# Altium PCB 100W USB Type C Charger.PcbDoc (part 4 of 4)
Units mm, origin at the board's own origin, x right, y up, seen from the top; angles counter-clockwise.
Board outline 79.45 x 55.68 mm, 4 copper layers (Top Layer, Signal Layer 1, Signal Layer 2, Bottom Layer), stack 1.565 mm thick; 161 components, 84 nets, 462 pads, 2175 vias.
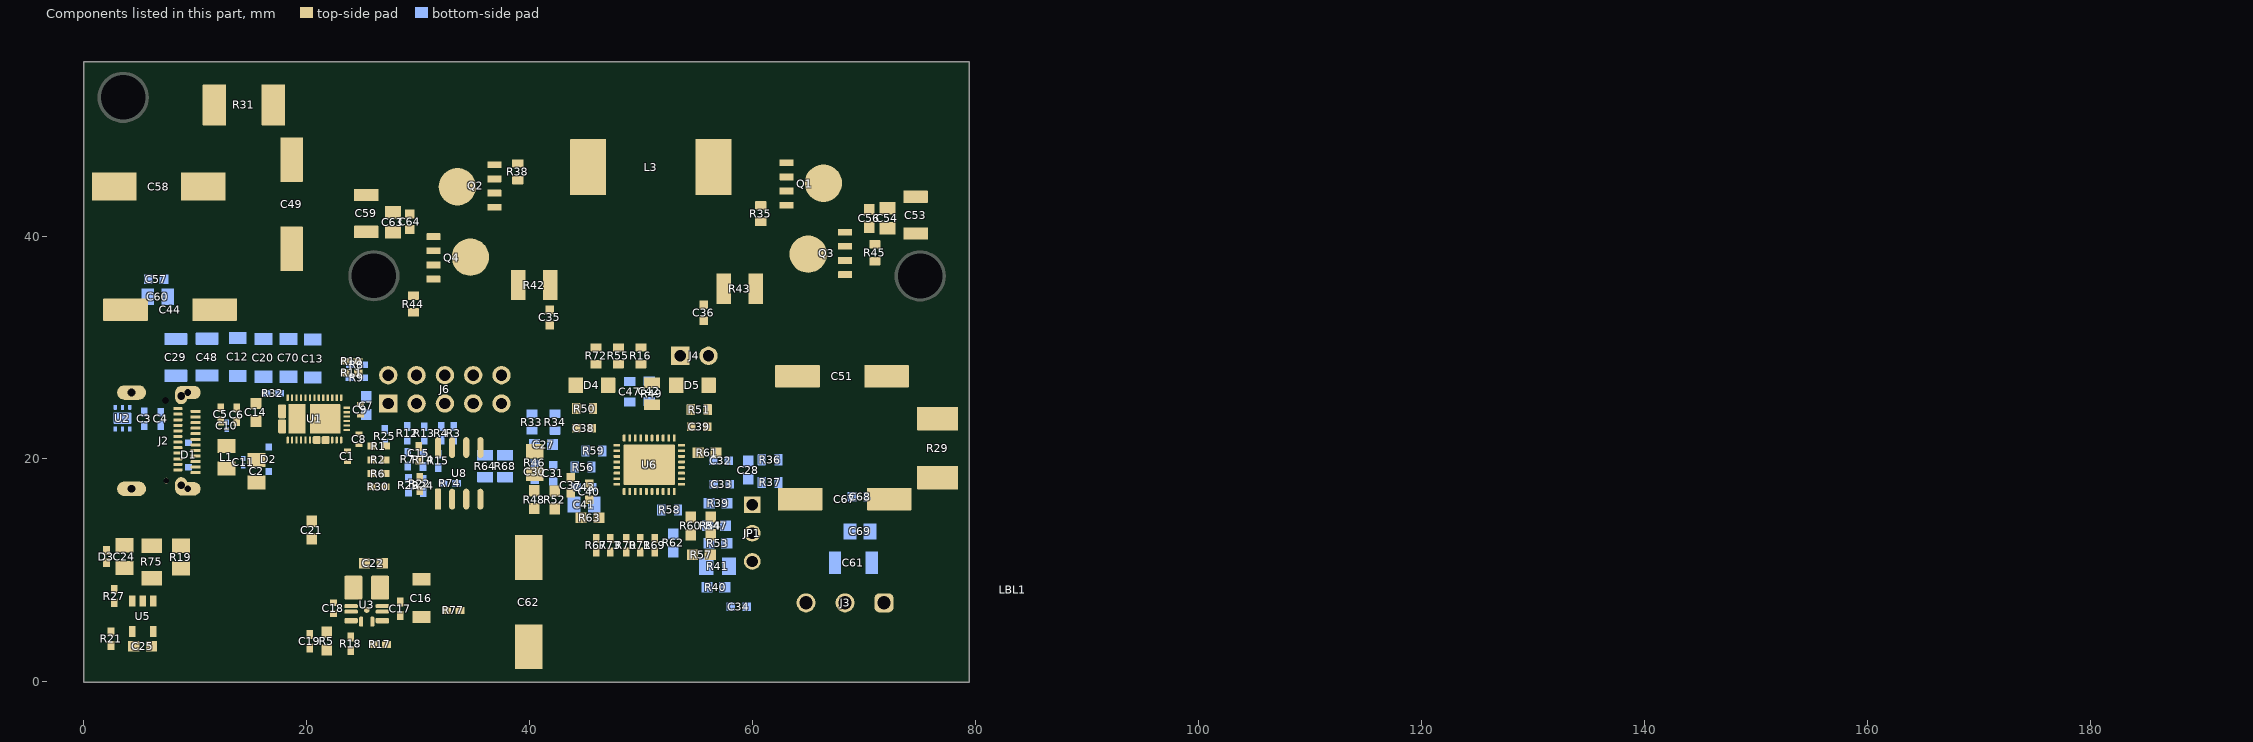
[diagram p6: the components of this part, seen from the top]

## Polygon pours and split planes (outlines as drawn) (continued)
P_OUT on Top Layer "TOP_LAYER_P_OUT_P025" (solid, remove dead copper, pour order 25): 64.308,55.009 64.308,42.909 65.504,41.712 78.892,41.712 78.892,55.009
BAT on Top Layer "TOP_LAYER_BAT_P031" (solid, remove dead copper, pour order 31): 69.769,19.315 69.769,3.891 78.786,3.891 78.786,19.315
PGND on Top Layer "TOP_LAYER_PGND_P051" (solid, remove dead copper, pour order 51): 20.124,28.919 20.088,22.281 22.294,22.281 22.294,18.928 24.265,16.29 29.666,16.29 30.674,14.94 35.587,14.94 38.268,17.523 38.323,28.919
PGND on Top Layer "TOP_LAYER_PGND_P070" (solid, remove dead copper, pour order 70): 40.305,29.689 40.305,15.334 45.197,10.441 59.614,10.441 59.614,29.689
PPHV on Top Layer "TOP_LAYER_PPHV_P010" (solid, remove dead copper, pour order 10): 8.093,29.311 14.717,29.311 14.717,22.461 19.339,22.461 19.339,27.565 21.505,29.722 21.505,34.447 8.093,34.447
PPHV on Top Layer "TOP_LAYER_PPHV_P011" (solid, remove dead copper, pour order 11): 8.237,55.009 8.237,41.433 13.317,41.433 13.317,55.009
VSYS on Top Layer "TOP_LAYER_VSYS_P013" (solid, remove dead copper, pour order 13): 35.556,55.009 35.556,41.255 15.374,41.255 15.374,55.009
SW1 on Top Layer "TOP_LAYER_SW1_P018" (solid, remove dead copper, pour order 18): 32.415,40.281 32.415,33.152 49.512,33.152 49.512,55.25 36.016,55.25 36.016,40.843 35.455,40.281
PGND on Top Layer "TOP_LAYER_PGND_P026" (solid, remove dead copper, pour order 26): 67.192,34.129 64.032,30.969 64.032,29.571 78.892,29.571 78.892,41.255 67.723,41.255 67.084,40.616
PGND on Top Layer "TOP_LAYER_PGND_P007" (solid, remove dead copper, pour order 7): 0.686,55.021 0.686,24.017 10.641,24.017 10.92,24.017 14.476,24.017 14.776,24.283 16.099,24.283 16.099,25.696 14.476,25.696 14.476,26.406 14.476,29.009 7.878,29.009 7.878,55.021
P_OUT on Top Layer "TOP_LAYER_P_OUT_P030" (solid, remove dead copper, pour order 30): 69.799,28.47 70.346,29.018 78.786,29.018 78.786,22.312 69.783,22.312
PGND on Top Layer "TOP_LAYER_PGND_P032" (solid, remove dead copper, pour order 32): 7.605,40.896 7.605,34.611 32.169,34.611 32.169,40.896
PGND on Top Layer "TOP_LAYER_PGND_P035" (solid, remove dead copper, pour order 35): 21.748,38.067 21.748,29.376 66.296,29.139 66.296,32.646 32.071,32.646 32.071,38.067
VBUS on Top Layer "TOP_LAYER_VBUS_P043" (solid, remove dead copper, pour order 43): 14.493,22.357 14.493,20.557 13.708,19.773 11.783,19.773 11.783,18.414 12.004,18.192 13.708,18.182 14.342,18.799 17.532,18.799 17.553,17.682 19.47,17.67 21.233,19.434 21.233,22.067 20.489,22.067 20.489,21.331 18.136,21.331 18.136,23.517 17.397,23.517 17.397,22.796 16.958,22.357
PGND on Top Layer "TOP_LAYER_PGND_P048" (solid, remove dead copper, pour order 48): 60.467,5.213 69.022,5.213 69.022,28.658 70.5,30.023 70.5,31.02 60.467,31.02
PGND on Bottom Layer "BOTTOM_LAYER_PGND_P088" (solid, remove dead copper, pour order 88): 39.728,29.238 39.728,15.063 44.575,10.216 60.138,10.216 60.138,29.238
PGND on Bottom Layer "BOTTOM_LAYER_PGND_P017" (solid, remove dead copper, pour order 17): 67.403,41.239 67.403,34.326 66.478,33.401 66.192,33.115 60.644,33.02 60.492,22.193 69.866,22.193 69.753,41.239
PGND on Bottom Layer "BOTTOM_LAYER_PGND_P004" (solid, remove dead copper, pour order 4): 0.341,55.709 0.537,20.782 2.256,20.782 2.256,23.157 3.091,23.157 4.268,23.157 5.063,23.766 11.382,23.776 11.382,22.968 14.513,22.968 14.513,24.375 16.032,24.375 16.494,24.837 23.951,24.837 23.951,29.715 7.033,29.715 6.312,30.436 6.312,55.709
PPHV on Bottom Layer "BOTTOM_LAYER_PPHV_P015" (solid, pour order 15): 6.843,30.622 7.743,29.722 21.67,29.722 21.67,31.606 18.829,34.447 15.548,34.447 13.317,36.678 13.317,55.009 6.843,55.009
P_OUT on Bottom Layer "BOTTOM_LAYER_P_OUT_P020" (solid, remove dead copper, pour order 20): 70.016,42.672 70.016,22.312 78.892,22.312 78.892,42.672
PGND on Bottom Layer "BOTTOM_LAYER_PGND_P047" (solid, remove dead copper, pour order 47): 36.901,30.126 38.942,28.086 38.942,16.008 37.632,14.698 24.322,14.698 23.874,15.146 23.874,30.126
Vdrain on Bottom Layer "BOTTOM_LAYER_VDRAIN_P045" (solid, remove dead copper, pour order 45): 18.233,25.023 18.233,22.432 19.784,22.432 19.786,22.434 19.786,25.032 19.759,25.059 18.269,25.059
PGND on Bottom Layer "BOTTOM_LAYER_PGND_P001" (solid, remove dead copper, pour order 1): 19.919,25.529 19.919,15.222 24.11,15.222 24.11,25.529
PPHV on Bottom Layer "BOTTOM_LAYER_PPHV_P003" (solid, remove dead copper, pour order 3): 14.726,22.871 17.403,22.871 18.194,23.708 18.183,25.024 16.857,25.024 16.016,24.183 14.726,24.183
P_OUT on Bottom Layer "BOTTOM_LAYER_P_OUT_P016" (solid, remove dead copper, pour order 16): 64.308,54.793 64.308,42.909 65.504,41.712 78.892,41.712 78.892,54.793
BAT on Bottom Layer "BOTTOM_LAYER_BAT_P021" (solid, remove dead copper, pour order 21): 70.016,20.265 70.016,5.695 78.768,5.695 78.768,20.265
PGND on Bottom Layer "BOTTOM_LAYER_PGND_P022" (solid, remove dead copper, pour order 22): 60.787,20.287 60.787,5.826 69.643,5.826 69.643,20.287
VSYS on Bottom Layer "BOTTOM_LAYER_VSYS_P023" (solid, remove dead copper, pour order 23): 35.587,55.009 35.587,41.122 14.868,41.122 14.868,55.009
SW1 on Bottom Layer "BOTTOM_LAYER_SW1_P024" (solid, remove dead copper, pour order 24): 32.669,40.543 32.669,33.152 49.512,33.152 49.512,55.009 36.016,55.009 36.016,41.058 35.501,40.543
SW2 on Bottom Layer "BOTTOM_LAYER_SW2_P027" (solid, remove dead copper, pour order 27): 60.874,33.203 65.28,33.203 67.102,35.025 67.102,40.259 66.121,41.239 65.403,41.239 63.774,42.868 63.774,55.009 52.217,55.009 52.217,33.203
PGND on Bottom Layer "BOTTOM_LAYER_PGND_P028" (solid, remove dead copper, pour order 28): 42.554,28.148 58.649,28.148 58.649,32.646 42.554,32.646
PGND on Bottom Layer "BOTTOM_LAYER_PGND_P034" (solid, remove dead copper, pour order 34): 14.868,37.677 17.063,35.405 19.742,35.29 23.506,31.526 32.038,31.526 32.038,40.8 14.868,40.8
PGND on Bottom Layer "BOTTOM_LAYER_PGND_P036" (solid, remove dead copper, pour order 36): 0.686,15.598 24.123,15.598 24.123,15.01 38.529,15.01 43.72,9.819 78.729,9.574 78.729,0.488 0.7,0.488
PGND on Bottom Layer "BOTTOM_LAYER_PGND_P038" (solid, remove dead copper, pour order 38): 2.28,19.548 2.28,20.968 0.686,20.968 0.686,15.508 20.274,15.508 20.274,19.611
NetC3_1 on Bottom Layer "BOTTOM_LAYER_NETC3_1_P000" (solid, remove dead copper, pour order 0): 2.493,22.908 2.493,19.756 11.148,19.756 11.148,23.581 5.168,23.581 4.495,22.908
BAT on Bottom Solder "NONET_L-01_P-001" (solid): 70.394,18.007 70.394,8.64 78.547,8.64 78.547,18.007
no net on Bottom Solder "NONET_L-01_P-001" (solid): 70.454,44.898 70.454,40.086 78.729,40.086 78.729,44.898
no net on Bottom Solder "NONET_L-01_P-001" (solid): 11.679,0.627 18.888,0.627 18.888,4.228 11.679,4.228
no net on Bottom Solder "NONET_L-01_P-001" (solid): 39.938,0.627 77.655,0.627 77.655,4.453 39.938,4.453
no net on Bottom Solder "NONET_L-01_P-001" (solid): 26.727,0.627 54.212,0.627 54.212,9.191 26.727,9.191
PGND on Bottom Solder "NONET_L-01_P-001" (solid): 17.88,13.948 24.557,13.948 24.557,18.673 17.88,18.673
PGND on Bottom Solder "NONET_L-01_P-001" (solid): 24.019,3.648 37.616,3.648 37.616,14.174 24.019,14.174
PGND on Bottom Solder "NONET_L-01_P-001" (solid): 10.852,9.837 20.268,9.837 20.268,17.579 10.852,17.579
no net on Bottom Solder "NONET_L-01_P-001" (solid): 70.459,31.445 70.459,23.372 78.612,23.372 78.612,31.445
SW1 on Bottom Solder "NONET_L-01_P-001" (solid): 32.977,39.863 32.977,33.735 39.525,33.735 39.525,39.863
no net on Bottom Solder "NONET_L-01_P-001" (solid): 36.643,54.564 36.643,46.643 44.2,46.643 44.2,54.564
PGND on Bottom Solder "NONET_L-01_P-001" (solid): 18.299,0.627 24.665,0.627 24.665,14.174 18.299,14.174
SW1 on Bottom Solder "NONET_L-01_P-001" (solid): 41.83,54.564 41.83,33.76 49.078,33.76 49.078,54.564
no net on Bottom Solder "NONET_L-01_P-001" (solid): 52.743,45.796 52.743,34.114 59.393,34.114 59.393,45.796
SW2 on Bottom Solder "NONET_L-01_P-001" (solid): 52.742,54.564 52.742,44.341 63.042,44.341 63.042,54.564
P_OUT on Bottom Solder "NONET_L-01_P-001" (solid): 64.841,54.564 64.841,43.007 65.795,42.054 78.768,42.054 78.768,54.564
VSYS on Bottom Solder "NONET_L-01_P-001" (solid): 15.451,54.564 15.451,42.194 34.806,42.194 34.806,54.564
no net on Top Solder "TOP_LAYER_PGND_P050" (solid): 20.407,15.65 22.425,15.65 22.425,17.955 20.407,17.955
no net on Top Solder "TOP_LAYER_PGND_P050" (solid): 70.395,3.704 78.105,3.704 78.105,14.381 70.395,14.381
VSYS on Top Solder "TOP_LAYER_PGND_P050" (solid): 15.679,49.459 20.193,49.459 20.193,54.651 15.679,54.651
VSYS on Top Solder "TOP_LAYER_PGND_P050" (solid): 19.987,44.43 30.196,44.43 30.196,47.909 19.987,47.909
BAT on Top Solder "TOP_LAYER_PGND_P050" (solid): 42.344,1.001 78.034,1.001 78.034,4.303 42.344,4.303
PGND on Top Solder "TOP_LAYER_PGND_P050" (solid): 72.763,34.145 78.593,34.145 78.593,39.549 72.763,39.549
PGND on Top Solder "TOP_LAYER_PGND_P050" (solid): 68.341,29.952 78.603,29.952 78.603,35.355 68.341,35.355
PGND on Top Solder "TOP_LAYER_PGND_P050" (solid): 22.282,29.722 28.301,29.722 28.301,39.519 22.282,39.519
PGND on Top Solder "TOP_LAYER_PGND_P050" (solid): 43.725,30.842 68.588,30.842 68.588,32.423 43.725,32.423
PGND on Top Solder "TOP_LAYER_PGND_P050" (solid): 26.566,29.712 43.905,29.712 43.905,32.388 26.566,32.388
SW2 on Top Solder "TOP_LAYER_PGND_P050" (solid): 56.677,48.326 63.459,48.326 63.459,54.64 56.677,54.64
SW1 on Top Solder "TOP_LAYER_PGND_P050" (solid): 36.634,48.24 42.901,48.24 42.901,54.564 36.634,54.564
SW1 on Top Solder "TOP_LAYER_PGND_P050" (solid): 42.057,38.112 48.743,38.112 48.743,54.564 42.057,54.564
SW2 on Top Solder "TOP_LAYER_PGND_P050" (solid): 52.776,38.067 59.207,38.067 59.207,54.64 52.776,54.64
VSYS on Top Solder "TOP_LAYER_PGND_P050" (solid): 20.001,46.854 34.874,46.854 34.874,54.64 20.001,54.64
P_OUT on Top Solder "TOP_LAYER_PGND_P050" (solid): 64.834,47.472 71.782,47.472 71.782,54.564 64.834,54.564
P_OUT on Top Solder "TOP_LAYER_PGND_P050" (solid): 69.781,43.619 78.278,43.619 78.278,54.564 69.781,54.564
PGND on Signal Layer 1 "SIGNAL_LAYER_1_PGND_P055" (solid, remove dead copper, pour order 55): 0.686,15.566 37.916,15.566 39.276,15.499 45.327,9.447 59.473,9.447 69.349,9.447 69.314,3.681 78.744,3.681 78.744,0.456 69.349,0.456 0.7,0.456
PGND on Signal Layer 1 "SIGNAL_LAYER_1_PGND_P090" (solid, remove dead copper, pour order 90): 39.546,28.967 39.546,15.875 45.702,9.72 60.119,9.72 60.119,28.967
PGND on Signal Layer 1 "SIGNAL_LAYER_1_PGND_P086" (solid, remove dead copper, pour order 86): 24.743,15.86 58.48,15.86 59.856,17.236 59.856,28.064 58.997,28.923 24.743,28.923
BAT on Signal Layer 1 "SIGNAL_LAYER_1_BAT_P071" (solid, remove dead copper, pour order 71): 69.817,17.988 69.817,4.204 78.786,4.204 78.786,17.988
PGND on Signal Layer 1 "SIGNAL_LAYER_1_PGND_P068" (solid, remove dead copper, pour order 68): 60.388,4.88 69.349,4.88 69.349,28.699 70.421,29.69 70.421,30.686 60.388,30.686
P_OUT on Signal Layer 1 "SIGNAL_LAYER_1_P_OUT_P067" (solid, remove dead copper, pour order 67): 69.885,28.383 70.433,28.931 78.768,28.931 78.768,22.225 69.87,22.225
SW2 on Signal Layer 1 "SIGNAL_LAYER_1_SW2_P064" (solid, remove dead copper, pour order 64): 65.669,33.465 66.86,34.656 66.86,39.981 65.897,40.944 65.266,40.944 63.824,42.386 63.824,54.793 52.267,54.793 52.267,33.465
PGND on Signal Layer 1 "SIGNAL_LAYER_1_PGND_P066" (solid, remove dead copper, pour order 66): 67.403,40.86 67.403,34.34 64.591,31.528 64.591,29.684 78.892,29.684 78.892,40.86
P_OUT on Signal Layer 1 "SIGNAL_LAYER_1_P_OUT_P065" (solid, remove dead copper, pour order 65): 64.283,54.793 64.283,42.46 65.504,41.239 78.768,41.239 78.768,54.793
PGND on Signal Layer 1 "SIGNAL_LAYER_1_PGND_P063" (solid, remove dead copper, pour order 63): 21.816,38.512 21.816,29.257 66.364,29.257 66.364,33.091 32.139,33.091 32.139,38.512
PGND on Signal Layer 1 "SIGNAL_LAYER_1_PGND_P062" (solid, remove dead copper, pour order 62): 7.666,40.953 7.666,35.036 32.169,35.036 32.169,40.953
PPHV on Signal Layer 1 "SIGNAL_LAYER_1_PPHV_P061" (solid, remove dead copper, pour order 61): 8.426,55.009 8.426,41.385 13.317,41.385 13.317,55.009
PPHV on Signal Layer 1 "SIGNAL_LAYER_1_PPHV_P058" (solid, pour order 58): 8.093,30.527 9.243,29.378 21.505,29.378 21.505,34.433 14.842,34.433 8.093,34.433
SW1 on Signal Layer 1 "SIGNAL_LAYER_1_SW1_P060" (solid, remove dead copper, pour order 60): 32.669,40.294 32.669,33.575 49.571,33.575 49.571,54.793 36.075,54.793 36.075,40.855 35.513,40.294
VSYS on Signal Layer 1 "SIGNAL_LAYER_1_VSYS_P059" (solid, remove dead copper, pour order 59): 35.533,54.793 35.533,41.458 14.868,41.458 14.868,54.793
PGND on Signal Layer 1 "SIGNAL_LAYER_1_PGND_P057" (solid, remove dead copper, pour order 57): 0.693,55.021 0.693,15.721 1.217,15.198 25.117,15.198 25.117,28.919 8.485,28.919 7.689,29.715 7.689,55.021
NetC3_1 on Signal Layer 1 "SIGNAL_LAYER_1_NETC3_1_P056" (solid, remove dead copper, pour order 56): 4.471,23.776 11.535,23.776 13.79,23.776 13.79,19.943 13.394,19.548 4.471,19.548
PGND on Signal Layer 2 "SIGNAL_LAYER_2_PGND_P079" (solid, remove dead copper, pour order 79): 21.816,38.512 21.748,29.584 69.799,29.584 69.799,39.766 67.723,39.766 67.723,34.823 66.233,32.996 32.139,33.091 32.139,38.512
PGND on Signal Layer 2 "SIGNAL_LAYER_2_PGND_P089" (solid, remove dead copper, pour order 89): 39.307,29.236 39.307,15.888 45.36,9.989 59.777,9.989 59.777,29.236
PGND on Signal Layer 2 "SIGNAL_LAYER_2_PGND_P072" (solid, remove dead copper, pour order 72): 0.686,15.566 39.319,15.359 45.287,9.629 69.619,9.629 69.619,3.794 78.786,3.794 78.786,0.456 69.349,0.456 0.7,0.456
PGND on Signal Layer 2 "SIGNAL_LAYER_2_PGND_P087" (solid, remove dead copper, pour order 87): 24.641,15.86 58.448,15.86 59.885,17.298 59.885,28.64 59.207,29.319 24.641,29.319
BAT on Signal Layer 2 "SIGNAL_LAYER_2_BAT_P085" (solid, remove dead copper, pour order 85): 70.072,17.988 70.072,4.204 78.786,4.204 78.786,17.988
PGND on Signal Layer 2 "SIGNAL_LAYER_2_PGND_P084" (solid, remove dead copper, pour order 84): 60.388,4.88 69.753,4.88 69.753,30.478 60.388,30.478
P_OUT on Signal Layer 2 "SIGNAL_LAYER_2_P_OUT_P083" (solid, remove dead copper, pour order 83): 70.162,39.777 70.162,41.712 79.2,41.712 79.2,22.225 70.162,22.225
P_OUT on Signal Layer 2 "SIGNAL_LAYER_2_P_OUT_P081" (solid, remove dead copper, pour order 81): 64.283,55.25 64.283,42.593 65.634,41.242 68.901,41.221 70.337,39.816 78.892,39.816 78.768,55.25
SW2 on Signal Layer 2 "SIGNAL_LAYER_2_SW2_P080" (solid, remove dead copper, pour order 80): 65.669,33.465 67.151,35.272 67.151,40.011 66.417,40.745 65.465,40.745 63.824,42.386 63.824,55.009 52.267,55.009 52.267,33.465
PGND on Signal Layer 2 "SIGNAL_LAYER_2_PGND_P078" (solid, remove dead copper, pour order 78): 7.666,40.953 7.666,35.036 32.169,35.036 32.169,40.953
PPHV on Signal Layer 2 "SIGNAL_LAYER_2_PPHV_P077" (solid, remove dead copper, pour order 77): 8.426,55.009 8.426,41.385 13.317,41.385 13.317,55.009
SW1 on Signal Layer 2 "SIGNAL_LAYER_2_SW1_P076" (solid, remove dead copper, pour order 76): 32.473,40.843 32.473,33.388 49.571,33.388 49.571,55.009 36.075,55.009 36.075,41.116 35.801,40.843
VSYS on Signal Layer 2 "SIGNAL_LAYER_2_VSYS_P075" (solid, remove dead copper, pour order 75): 35.533,55.009 35.533,41.458 14.868,41.458 14.868,55.009
PPHV on Signal Layer 2 "SIGNAL_LAYER_2_PPHV_P074" (solid, pour order 74): 8.093,29.378 21.505,29.378 21.505,34.433 14.842,34.433 8.093,34.433
PGND on Signal Layer 2 "SIGNAL_LAYER_2_PGND_P073" (solid, remove dead copper, pour order 73): 0.693,55.021 0.693,15.01 25.117,15.01 25.117,28.357 24.691,28.783 8.104,28.783 7.689,29.198 7.689,55.021

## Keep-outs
Keep-Out Layer:
  text ".Layer_Name" at -11.372,-55.887 h0.3

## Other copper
Top Layer:
  text "Layer" at 105.298,42.769 h1.52
  text "Name" at 115.71,42.769 h1.52
  text "Material" at 139.579,42.769 h1.52
  text "Thickness" at 161.418,42.769 h1.52
  text "Constant" at 177.923,42.769 h1.52
  text "Top Overlay" at 115.71,39.721 h1.52
  text "Top Solder" at 115.71,36.673 h1.52
  text "Solder Resist" at 139.579,36.673 h1.52
  text "0.010mm" at 161.418,36.673 h1.52
  text "3.5" at 177.923,36.673 h1.52
  text "1" at 105.298,33.625 h1.52
  text "Top Layer" at 115.71,33.625 h1.52
  text "0.036mm" at 161.418,33.625 h1.52
  text "Dielectric 1" at 115.71,30.577 h1.52
  text "FR-4 High Tg" at 139.579,30.577 h1.52
  text "0.203mm" at 161.418,30.577 h1.52
  text "4.2" at 177.923,30.577 h1.52
  text "2" at 105.298,27.529 h1.52
  text "Signal Layer 1" at 115.71,27.529 h1.52
  text "0.036mm" at 161.418,27.529 h1.52
  text "Dielectric 2" at 115.71,24.481 h1.52
  text "FR-4 High Tg" at 139.579,24.481 h1.52
  text "1.016mm" at 161.418,24.481 h1.52
  text "4.2" at 177.923,24.481 h1.52
  text "3" at 105.298,21.433 h1.52
  text "Signal Layer 2" at 115.71,21.433 h1.52
  text "0.036mm" at 161.418,21.433 h1.52
  text "Dielectric 3" at 115.71,18.385 h1.52
  text "FR-4 High Tg" at 139.579,18.385 h1.52
  text "0.203mm" at 161.418,18.385 h1.52
  text "4.2" at 177.923,18.385 h1.52
  text "4" at 105.298,15.337 h1.52
  text "Bottom Layer" at 115.71,15.337 h1.52
  text "0.036mm" at 161.418,15.337 h1.52
  text "Bottom Solder" at 115.71,12.289 h1.52
  text "Solder Resist" at 139.579,12.289 h1.52
  text "0.010mm" at 161.418,12.289 h1.52
  text "3.5" at 177.923,12.289 h1.52
  text "Bottom Overlay" at 115.71,9.241 h1.52
  text "Total board thickness:" at 105.298,6.193 h1.52
  text "1.585mm" at 161.418,6.193 h1.52
  text ".Layer_Name" at -11.372,-55.887 h0.3
Bottom Layer:
  text ".Layer_Name" at -11.372,-55.887 h0.3

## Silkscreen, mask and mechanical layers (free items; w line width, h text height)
Top Overlay:
  text "'.PRJ_Number'.PCB_Rev" at 63.207,1.271 h1
  text ".Layer_Name" at -11.372,-55.887 h0.3
Bottom Overlay:
  text ".Layer_Name" at -11.372,-55.887 h0.3
Top Paste:
  text ".Layer_Name" at -11.372,-55.887 h0.3
Bottom Paste:
  text ".Layer_Name" at -11.372,-55.887 h0.3
Top Solder:
  text ".Layer_Name" at -11.372,-55.887 h0.3
  text ".Layer_Name" at -11.372,-55.887 h0.3
Bottom Solder:
  text ".Layer_Name" at -11.372,-55.887 h0.3
Drill Guide:
  text ".Layer_Name" at -11.372,-55.887 h0.3
M1 Board Outline:
  the board outline again, w0.254
  text ".Layer_Name" at -11.372,-55.887 h0.3
M2 Board Dimensions:
  rectangle: -22.852,-44.242 -13.327,-41.067
  rectangle: -26.027,-41.067 -22.852,-37.892
  lines w0.178: -26.027,-41.067 -0.627,-41.067 ; -22.852,-44.242 -22.852,-37.892 ; -19.677,-44.242 -19.677,-37.892 ; -13.327,-44.242 -13.327,-37.892 ; -6.977,-44.242 -6.977,-37.892 ; -26.027,-44.242 -26.027,-37.892 -0.627,-37.892 -0.627,-44.242 -26.027,-44.242
  text ".Layer_Name" at -11.372,-55.887 h0.3
M3 3D STEP Top:
  text ".Layer_Name" at -11.372,-55.887 h0.3
M4 3D STEP Bottom:
  text ".Layer_Name" at -11.372,-55.887 h0.3
Top M5 Assembly Top/M6 Assembly Bottom:
  lines w0.254: -33.444,-57.708 134.196,-57.708 ; -33.444,-52.543 134.247,-52.543 ; -33.444,-47.379 -33.444,-62.873 68.283,-62.873 134.247,-62.873 134.247,-47.379 -33.431,-47.379 -33.431,-62.873 6.586,-62.873 ; 29.167,-62.873 29.167,-47.379 ; 61.349,-52.543 61.349,-47.379 ; 82.685,-52.543 82.685,-47.379 ; 98.483,-63.038 98.483,-57.886
  text "COMPONENTS MARKED 'DNP' SHOULD NOT BE POPULATED." at 3.272,-42.172 h0.3
  text "ASSEMBLY VARIANT:" at 3.259,-45.105 h0.3
  text ".VariantName" at 29.573,-45.105 h0.3
  text "PCB VIEWED FROM TOP SIDE" at -31.831,-50.736 h0.3
  text "BOARD #:" at 31.072,-50.736 h0.3
  text ".PRJ_Number" at 44.928,-50.736 h0.3
  text "REV:" at 66.378,-50.736 h0.3
  text ".PCB_Rev" at 73.782,-50.736 h0.3
  text "SVN REV:" at 87.663,-50.736 h0.3
  text ".VersionControl_RevNumber" at 100.515,-50.736 h0.3
  text "PLOT NAME =" at -31.831,-61.116 h0.3
  text ".plot_File_Name" at -11.372,-61.116 h0.3
  text "GENERATED    :" at 31.123,-61.116 h0.3
  text ".Print_Date" at 53.208,-61.116 h0.3
  text ".Print_Time" at 71.725,-61.116 h0.3
  text "TEXAS INSTRUMENTS" at 103.843,-61.116 h0.3
Bottom M5 Assembly Top/M6 Assembly Bottom:
  lines w0.254: -33.457,-52.556 134.234,-52.556 ; -33.406,-57.721 134.234,-57.721 ; 2.306,-63.05 2.306,-57.898 ; 18.105,-52.556 18.105,-47.391 ; 39.441,-52.556 39.441,-47.391 ; 71.623,-62.885 71.623,-47.391 ; 94.204,-62.885 134.221,-62.885 134.221,-47.391 -33.457,-47.391 -33.457,-62.885 32.507,-62.885 134.234,-62.885 134.234,-47.391
  text "COMPONENTS MARKED 'DNP' SHOULD NOT BE POPULATED." at 128.963,-42.159 h0.3
  text ".VariantName" at 102.446,-45.105 h0.3
  text "ASSEMBLY VARIANT:" at 128.836,-45.105 h0.3
  text ".VersionControl_RevNumber" at 0.274,-50.748 h0.3
  text "SVN REV:" at 13.127,-50.748 h0.3
  text ".PCB_Rev" at 27.008,-50.748 h0.3
  text "REV:" at 34.412,-50.748 h0.3
  text ".PRJ_Number" at 55.862,-50.748 h0.3
  text "BOARD #:" at 69.718,-50.748 h0.3
  text "PCB VIEWED FROM BOTTOM SIDE" at 132.621,-50.748 h0.3
  text "TEXAS INSTRUMENTS" at -3.053,-61.129 h0.3
  text ".Print_Time" at 29.065,-61.129 h0.3
  text ".Print_Date" at 47.582,-61.129 h0.3
  text "GENERATED    :" at 69.667,-61.129 h0.3
  text ".plot_File_Name" at 112.161,-61.129 h0.3
  text "PLOT NAME =" at 132.621,-61.129 h0.3
M9 Title Sheet:
  drawing of 63 lines, arcs and shapes, not listed
  text "1" at 9.266,432.669 h0.3
  text "2" at 110.739,432.669 h0.3
  text "3" at 212.212,432.669 h0.3
  text "4" at 313.838,432.669 h0.3
  text "5" at 415.395,432.669 h0.3
  text "6" at 516.953,432.669 h0.3
  text "7" at 618.595,432.669 h0.3
  text "8" at 720.068,432.669 h0.3
  text "A" at -37.902,371.759 h0.3
  text "A" at 767.278,371.759 h0.3
  text "B" at -37.902,244.759 h0.3
  text "B" at 767.278,244.759 h0.3
  text "C" at -37.902,117.759 h0.3
  text "C" at 767.278,117.759 h0.3
  text "D" at -37.902,-9.241 h0.3
  text "D" at 767.278,-9.241 h0.3
  text "PROJECT TITLE:" at 688.919,-27.259 h0.3
  text ".PRJ_Title" at 690.189,-30.646 h0.3
  text "DESIGNED FOR:" at 688.919,-34.904 h0.3
  text ".PRJ_Customer" at 690.189,-38.46 h0.3
  text "FILE NAME:" at 688.919,-42.524 h0.3
  text ".PCB_File_Name_No_Path" at 690.189,-45.572 h0.3
  text "Texas Instruments (TI) and/or its licensors do not warrant the accuracy or completeness of this specification" at 562.694,-49.683 h0.3
  text "ENGINEER:" at 688.919,-49.89 h0.3
  text "LAYOUT BY:" at 727.146,-49.89 h0.3
  text "or any information contained therein. TI and/or its licensors do not warrant that this design will meet" at 561.551,-52.545 h0.3
  text ".PRJ_Engineer" at 690.189,-53.827 h0.3
  text ".PCB_Layout" at 728.429,-53.827 h0.3
  text "the specifications, will be suitable for your application or fit for any particular purpose, or will operate in" at 561.551,-55.407 h0.3
  text ".Layer_Name" at -11.372,-55.887 h0.3
  text "ALTIUM DESIGNER VERSION:" at 727.146,-57.764 h0.3
  text "an implementation. TI and/or its licensors do not warrant that the design is production worthy. You should" at 561.551,-58.268 h0.3
  text "completely validate and test your design implementation to confirm the system functionality for your application." at 562.694,-61.13 h0.3
  text ".print_Scale" at 690.189,-61.151 h0.3
  text ".Application_BuildNumber" at 728.429,-61.151 h0.3
  text "1" at 9.266,-67.584 h0.3
  text "2" at 110.739,-67.584 h0.3
  text "3" at 212.212,-67.584 h0.3
  text "4" at 313.838,-67.584 h0.3
  text "5" at 415.395,-67.584 h0.3
  text "6" at 516.953,-67.584 h0.3
  text "7" at 618.595,-67.584 h0.3
  text "8" at 720.068,-67.584 h0.3
M10 Fab Notes:
  drawing of 189 lines, arcs and shapes, not listed
  text "DESIGN INFORMATION" at 715.348,127.594 h0.3
  text "MIN. TRACK WIDTH:" at 698.976,124.238 h0.3
  text "8" at 726.821,124.238 h0.3
  text "MIL" at 730.752,124.238 h0.3
  text "MIN. CLEARANCE:" at 698.976,121.085 h0.3
  text "7.874" at 722.473,121.085 h0.3
  text "MIL" at 730.752,121.085 h0.3
  text "MIN. VIA PAD SIZE:" at 698.976,117.932 h0.3
  text "24" at 726.059,117.932 h0.3
  text "MIL" at 730.752,117.932 h0.3
  text "0.05mm (2MIL)" at 716.629,114.633 h0.3
  text "MINIMUM ANNULAR RING" at 690.614,114.424 h0.3
  text "EXTERNAL" at 734.613,114.424 h0.3
  text "PER" at 695.694,111.627 h0.3
  text "IPC-D-275 CLASS 2 LEVEL C" at 701.282,111.627 h0.3
  text "MIL, HOLES" at 739.083,109.074 h0.3
  text "+/-" at 729.115,108.856 h0.3
  text "+/-" at 750.806,108.856 h0.3
  text "REGISTRATION TOLERANCES:" at 690.614,108.829 h0.3
  text "METAL" at 721.088,108.829 h0.3
  text "5" at 735.724,108.829 h0.3
  text "3" at 756.882,108.829 h0.3
  text "MIL" at 759.835,108.829 h0.3
  text "HOLE SIZE TOLERANCE (UNLESS OTHERWISE SPECIFIED):" at 690.614,106.332 h0.3
  text "+/-" at 750.806,106.259 h0.3
  text "3" at 756.882,106.232 h0.3
  text "MIL" at 759.835,106.232 h0.3
  text "MATERIAL:" at 688.715,102.736 h0.3
  text "FR-4 High Tg" at 713.771,99.471 h0.3
  text "X" at 710.102,99.268 h0.3
  text "FR-4" at 699.408,99.154 h0.3
  text "OTHER" at 737.203,99.154 h0.3
  text "62 MIL (1.6mm) +/-10%" at 707.539,95.521 h0.3
  text "X" at 704.488,95.458 h0.3
  text "THICKNESS:" at 690.614,95.312 h0.3
  text "OTHER" at 740.175,95.312 h0.3
  text "TOLERANCE:" at 690.614,91.799 h0.3
  text "X" at 712.159,91.799 h0.3
  text "ANSI IPC-6012 TYPE 3 CLASS 2" at 716.681,91.799 h0.3
  text "OTHER +/-" at 716.68,88.136 h0.3
  text "BOW & TWIST:" at 690.614,84.449 h0.3
  text "X" at 712.159,84.449 h0.3
  text "ANSI IPC-6012 TYPE 3 CLASS 2" at 716.681,84.449 h0.3
  text "OTHER +/-" at 716.68,80.722 h0.3
  text "DRILLING:" at 688.715,77.405 h0.3
  text "NC_DRILL FILES" at 733.444,74.733 h0.3
  text "REFERENCE:" at 690.614,74.633 h0.3
  text "X" at 707.308,74.63 h0.3
  text "AS SHOWN" at 711.829,74.633 h0.3
  text "X" at 730.193,74.633 h0.3
  text "OTHER" at 741.013,71.02 h0.3
  text "PTH COPPER THICKNESS:" at 690.606,70.93 h0.3
  text "X" at 719.542,70.93 h0.3
  text "20-30 um" at 722.793,70.93 h0.3
  text "BOARD FINISH:" at 688.715,67.181 h0.3
  text "SILKSCREEN:" at 692.658,64.384 h0.3
  text "X" at 716.985,64.384 h0.3
  text "TOP" at 719.957,64.384 h0.3
  text "X" at 729.939,64.384 h0.3
  text "BOTTOM" at 732.936,64.384 h0.3
  text "SILKSCREEN COLOR:" at 692.658,60.442 h0.3
  text "X" at 716.96,60.442 h0.3
  text "WHITE" at 719.957,60.442 h0.3
  text "OTHER" at 732.936,60.442 h0.3
  text "X" at 720.287,56.799 h0.3
  text "GREEN" at 723.284,56.799 h0.3
  text "OTHER" at 738.981,56.799 h0.3
  text "SOLDER RESIST COLOR:" at 692.658,56.624 h0.3
  text "X" at 720.287,52.881 h0.3
  text "MATTE" at 723.284,52.881 h0.3
  text "SEMI-GLOSS" at 738.97,52.864 h0.3
  text "IMMERSION GOLD (ENIG)" at 715.664,48.492 h0.3
  text "ENEPIG" at 749.638,48.309 h0.3
  text "SURFACE FINISH:" at 688.715,48.283 h0.3
  text "X" at 711.143,48.283 h0.3
  text "IMM. TIN/SILVER OR EQUIV" at 697.085,44.796 h0.3
  text "OTHER" at 733.444,44.696 h0.3
  text "ARRAY/PANEL:" at 688.715,40.749 h0.3
  text "CUT AND TRIM PER M1 BOARD OUTLINE" at 715.664,40.54 h0.3
  text "N.C. ROUTE" at 715.664,37.086 h0.3
  text "X" at 733.14,37.086 h0.3
  text "V. SCORE" at 737.661,37.086 h0.3
  text "CERTIFICATION:" at 688.715,33.807 h0.3
  text "MATERIALS AND WORKMANSHIP FOR ALL PCBS" at 707.13,33.807 h0.3
  text "TO MEET OR EXCEED THE REQUIREMENTS OF:" at 707.13,31.417 h0.3
  text "X" at 697.923,28.15 h0.3
  text "ANSI IPC-A-600F CLASS ->" at 701.174,28.15 h0.3
  text "X" at 743.033,28.15 h0.3
  text "2" at 745.827,28.15 h0.3
  text "1" at 737.826,28.112 h0.3
  text "3" at 754.818,28.112 h0.3
  text "X" at 718.547,24.399 h0.3
  text "RoHS" at 721.798,24.399 h0.3
  text "OTHER" at 738.166,24.399 h0.3
  text "PER ORDER" at 748.252,24.399 h0.3
  text "ALL BOARDS MUST MEET OR EXCEED UL94-V0 REQUIREMENTS." at 689.414,20.492 h0.3
  text "PCB MUST BEAR THE UL94V-0 UL REGISTERED MATERIAL ID NUMBER" at 689.414,17.544 h0.3
  text "ADDITIONAL REQUIREMENTS:" at 688.715,13.24 h0.3
  text "MICROSECTION:" at 690.614,10.519 h0.3
  text "YES" at 713.62,10.519 h0.3
  text "REQUIRED" at 735.502,6.853 h0.3
  text "BARE BOARD ELEC. TEST:" at 690.614,6.781 h0.3
  text "NONE" at 723.78,6.781 h0.3
  text "X" at 732.505,6.781 h0.3
  text "PER ORDER" at 750.538,6.781 h0.3
  text "XX MIL VIAS REQUIRE NON-CONDUCTIVE FILL AND PLANARIZE" at 694.885,1.575 h0.3
  text "XX MIL VIAS REQUIRE CONDUCTIVE FILL AND PLANARIZE" at 695.088,-1.066 h0.3
  text "OUTER XX MIL TRACES REQUIRE 50 OHM SINGLE-ENDED IMPEDANCE" at 695.063,-5.216 h0.3
  text "LAYER 2 & 3 (INNER LAYERS) XX MIL WIDE, XX MIL SPACE / TRACES REQUIRE 100 OHM DIFFERENTIAL IMPEDANCE" at 694.86,-11.203 h0.3
  text ".Layer_Name" at -11.372,-55.887 h0.3
M11 Gerber Information:
  lines w0.254: -33.444,-57.708 134.196,-57.708 ; -33.444,-52.543 134.247,-52.543 ; -33.444,-47.379 -33.444,-62.873 68.283,-62.873 134.247,-62.873 134.247,-47.379 -33.431,-47.379 -33.431,-62.873 6.586,-62.873 ; 29.167,-62.873 29.167,-47.379 ; 61.349,-52.543 61.349,-47.379 ; 82.685,-52.543 82.685,-47.379 ; 98.483,-63.038 98.483,-57.886
  text "ALL ARTWORK VIEWED FROM TOP SIDE" at -31.831,-50.736 h0.3
  text "BOARD #:" at 31.072,-50.736 h0.3
  text ".PRJ_Number" at 44.928,-50.736 h0.3
  text "REV:" at 66.378,-50.736 h0.3
  text ".PCB_Rev" at 73.782,-50.736 h0.3
  text "SVN REV:" at 87.663,-50.736 h0.3
  text ".VersionControl_RevNumber" at 100.515,-50.736 h0.3
  text "LAYER NAME =" at -31.831,-55.887 h0.3
  text "PLOT NAME =" at -31.831,-61.116 h0.3
  text ".plot_File_Name" at -11.372,-61.116 h0.3
  text "GENERATED    :" at 31.123,-61.116 h0.3
  text ".Print_Date" at 53.208,-61.116 h0.3
  text ".Print_Time" at 71.725,-61.116 h0.3
  text "TEXAS INSTRUMENTS" at 103.843,-61.116 h0.3
M12 Stackup:
  drawing of 317 lines, arcs and shapes, not listed
  text "Layer" at 647.217,425.278 h0.3
  text "Name" at 649.675,425.278 h0.3
  text "Material" at 654.781,425.278 h0.3
  text "Thickness" at 659.488,425.278 h0.3
  text "Constant" at 663.145,425.278 h0.3
  text "Board Layer Stack" at 666.403,425.278 h0.3
  text "Top Overlay" at 649.675,424.678 h0.3
  text "Top Solder" at 649.675,424.078 h0.3
  text "Solder Resist" at 654.781,424.078 h0.3
  text "0.40mil" at 659.488,424.078 h0.3
  text "3.5" at 663.145,424.078 h0.3
  text "1" at 647.217,423.478 h0.3
  text "Top Layer" at 649.675,423.478 h0.3
  text "1.40mil" at 659.488,423.478 h0.3
  text "Dielectric 1" at 649.675,422.878 h0.3
  text "FR-4 High Tg" at 654.781,422.878 h0.3
  text "8.00mil" at 659.488,422.878 h0.3
  text "4.2" at 663.145,422.878 h0.3
  text "2" at 647.217,422.278 h0.3
  text "Signal Layer 1" at 649.675,422.278 h0.3
  text "1.40mil" at 659.488,422.278 h0.3
  text "Dielectric 2" at 649.675,421.678 h0.3
  text "FR-4 High Tg" at 654.781,421.678 h0.3
  text "40.00mil" at 659.488,421.678 h0.3
  text "4.2" at 663.145,421.678 h0.3
  text "3" at 647.217,421.078 h0.3
  text "Signal Layer 2" at 649.675,421.078 h0.3
  text "1.40mil" at 659.488,421.078 h0.3
  text "Dielectric 3" at 649.675,420.478 h0.3
  text "FR-4 High Tg" at 654.781,420.478 h0.3
  text "8.00mil" at 659.488,420.478 h0.3
  text "4.2" at 663.145,420.478 h0.3
  text "4" at 647.217,419.878 h0.3
  text "Bottom Layer" at 649.675,419.878 h0.3
  text "1.40mil" at 659.488,419.878 h0.3
  text "Bottom Solder" at 649.675,419.278 h0.3
  text "Solder Resist" at 654.781,419.278 h0.3
  text "0.40mil" at 659.488,419.278 h0.3
  text "3.5" at 663.145,419.278 h0.3
  text "Bottom Overlay" at 649.675,418.678 h0.3
  text ".Layer_Name" at -11.372,-55.887 h0.3
M13 Component Bodies Top:
  text ".Layer_Name" at -11.372,-55.887 h0.3
M14 Component Bodies Bottom:
  text ".Layer_Name" at -11.372,-55.887 h0.3
M15 Courtyards Top:
  text ".Layer_Name" at -11.372,-55.887 h0.3
M16 Courtyards Bottom:
  text ".Layer_Name" at -11.372,-55.887 h0.3
Drill Drawing:
  circle w0.254: c2.228,103.205 r0.421
  circle w0.254: c2.228,103.205 r0.702
  circle w0.254: c2.228,84.258 r0.702
  lines w0.254: 1.526,77.241 2.93,77.241 2.93,78.645 1.526,78.645 1.526,77.241 ; 1.526,80.399 2.93,80.399 2.93,81.802 1.526,81.802 1.526,80.399 ; 1.526,86.714 1.526,87.065 1.877,87.416 1.526,87.767 1.526,88.118 1.877,88.118 2.228,87.767 2.579,88.118 2.93,88.118 2.93,87.767 2.579,87.416 2.93,87.065 2.93,86.714 2.579,86.714 2.228,87.065 1.877,86.714 1.526,86.714 ; 1.526,90.223 1.877,90.223 2.228,89.872 2.579,90.223 2.93,90.223 2.579,90.574 2.93,90.925 2.579,90.925 2.228,91.276 1.877,90.925 1.526,90.925 1.877,90.574 1.526,90.223 ; 1.526,94.433 2.93,94.433 2.228,93.03 1.526,94.433 ; 1.526,96.188 2.228,96.538 2.93,96.188 2.579,96.889 2.93,97.591 2.228,97.24 1.526,97.591 1.877,96.889 1.526,96.188 ; 1.526,99.696 1.877,99.696 1.877,99.345 2.579,99.345 2.579,99.696 2.93,99.696 2.93,100.398 2.579,100.398 2.579,100.749 1.877,100.749 1.877,100.398 1.526,100.398 1.526,99.696 ; 1.526,106.363 2.228,105.661 2.93,106.363 2.228,107.064 1.526,106.363 ; 1.807,77.522 2.649,77.522 2.649,78.364 1.807,78.364 1.807,77.522
  lines w0.305: 0.254,76.294 80.455,76.294 ; 0.254,107.871 80.455,107.871 ; 8.836,73.136 8.836,111.029 ; 16.493,73.136 16.493,111.029 ; 31.559,73.136 31.559,111.029 ; 38.141,73.136 38.141,111.029 ; 47.67,73.136 47.67,111.029 ; 66.068,73.136 66.068,111.029 ; 0.254,73.136 80.455,73.136 80.455,111.029 0.254,111.029 0.254,73.136
  text "Symbol" at 2.149,108.819 h1.83
  text "Count" at 9.783,108.819 h1.83
  text "Hole Size" at 17.44,108.819 h1.83
  text "Plated" at 32.506,108.819 h1.83
  text "Hole Type" at 39.088,108.819 h1.83
  text "Drill Layer Pair" at 48.617,108.819 h1.83
  text "Hole Tolerance" at 67.015,108.819 h1.83
  text "200" at 9.783,105.661 h1.52
  text "0.200mm (7.87mil)" at 17.44,105.661 h1.52
  text "PTH" at 32.506,105.661 h1.52
  text "Round" at 39.088,105.661 h1.52
  text "Top Layer - Bottom Layer" at 48.617,105.661 h1.52
  text "627" at 9.783,102.503 h1.52
  text "0.330mm (13.00mil)" at 17.44,102.503 h1.52
  text "PTH" at 32.506,102.503 h1.52
  text "Round" at 39.088,102.503 h1.52
  text "Top Layer - Bottom Layer" at 48.617,102.503 h1.52
  text "1" at 9.783,99.345 h1.52
  text "0.500mm (19.69mil)" at 17.44,99.345 h1.52
  text "NPTH" at 32.506,99.345 h1.52
  text "Slot" at 39.088,99.345 h1.52
  text "Top Layer - Bottom Layer" at 48.617,99.345 h1.52
  text "+/-0.030mm" at 67.015,99.345 h1.52
  text "1" at 9.783,96.188 h1.52
  text "0.600mm (23.62mil)" at 17.44,96.188 h1.52
  text "NPTH" at 32.506,96.188 h1.52
  text "Round" at 39.088,96.188 h1.52
  text "Top Layer - Bottom Layer" at 48.617,96.188 h1.52
  text "+/-0.030mm" at 67.015,96.188 h1.52
  text "2" at 9.783,93.03 h1.52
  text "0.600mm (23.62mil)" at 17.44,93.03 h1.52
  text "PTH" at 32.506,93.03 h1.52
  text "Slot" at 39.088,93.03 h1.52
  text "Top Layer - Bottom Layer" at 48.617,93.03 h1.52
  text "+/-0.050mm" at 67.015,93.03 h1.52
  text "2" at 9.783,89.872 h1.52
  text "0.700mm (27.56mil)" at 17.44,89.872 h1.52
  text "PTH" at 32.506,89.872 h1.52
  text "Slot" at 39.088,89.872 h1.52
  text "Top Layer - Bottom Layer" at 48.617,89.872 h1.52
  text "+/-0.050mm" at 67.015,89.872 h1.52
  text "2" at 9.783,86.714 h1.52
  text "0.700mm (27.56mil)" at 17.44,86.714 h1.52
  text "PTH" at 32.506,86.714 h1.52
  text "Slot" at 39.088,86.714 h1.52
  text "Top Layer - Bottom Layer" at 48.617,86.714 h1.52
  text "+/-0.050mm" at 67.015,86.714 h1.52
  text "15" at 9.783,83.557 h1.52
  text "1.016mm (40.00mil)" at 17.44,83.557 h1.52
  text "PTH" at 32.506,83.557 h1.52
  text "Round" at 39.088,83.557 h1.52
  text "Top Layer - Bottom Layer" at 48.617,83.557 h1.52
  text "3" at 9.783,80.399 h1.52
  text "1.200mm (47.24mil)" at 17.44,80.399 h1.52
  text "PTH" at 32.506,80.399 h1.52
  text "Round" at 39.088,80.399 h1.52
  text "Top Layer - Bottom Layer" at 48.617,80.399 h1.52
  text "3" at 9.783,77.241 h1.52
  text "4.000mm (157.48mil)" at 17.44,77.241 h1.52
  text "PTH" at 32.506,77.241 h1.52
  text "Round" at 39.088,77.241 h1.52
  text "Top Layer - Bottom Layer" at 48.617,77.241 h1.52
  text "856 Total" at 9.783,74.084 h1.52
  text "Slot definitions :" at 2.149,71.873 h1.52
  text "Routed Path Length" at 13.597,71.873 h1.52
  text "= Calculated from tool start centre position to tool end centre position." at 27.306,71.873 h1.52
  text "Hole Length" at 13.597,70.61 h1.52
  text "= Routed Path Length + Tool Size = Slot length as defined in the PCB layout" at 22.231,70.61 h1.52
  text ".Layer_Name" at -11.372,-55.887 h0.3
M17 Embedded Cavity:
  text ".Layer_Name" at -11.372,-55.887 h0.3
M18 Embedded Assembly:
  text ".Layer_Name" at -11.372,-55.887 h0.3
M19 Embedded Keepout:
  text ".Layer_Name" at -11.118,-55.633 h0.3

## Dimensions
-0.018,-0.02 to -0.018,55.656 on M2 Board Dimensions
-0.018,-0.02 to 79.433,-0.02 on M2 Board Dimensions
-26.027,-44.242 to -0.627,-44.242 on M2 Board Dimensions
